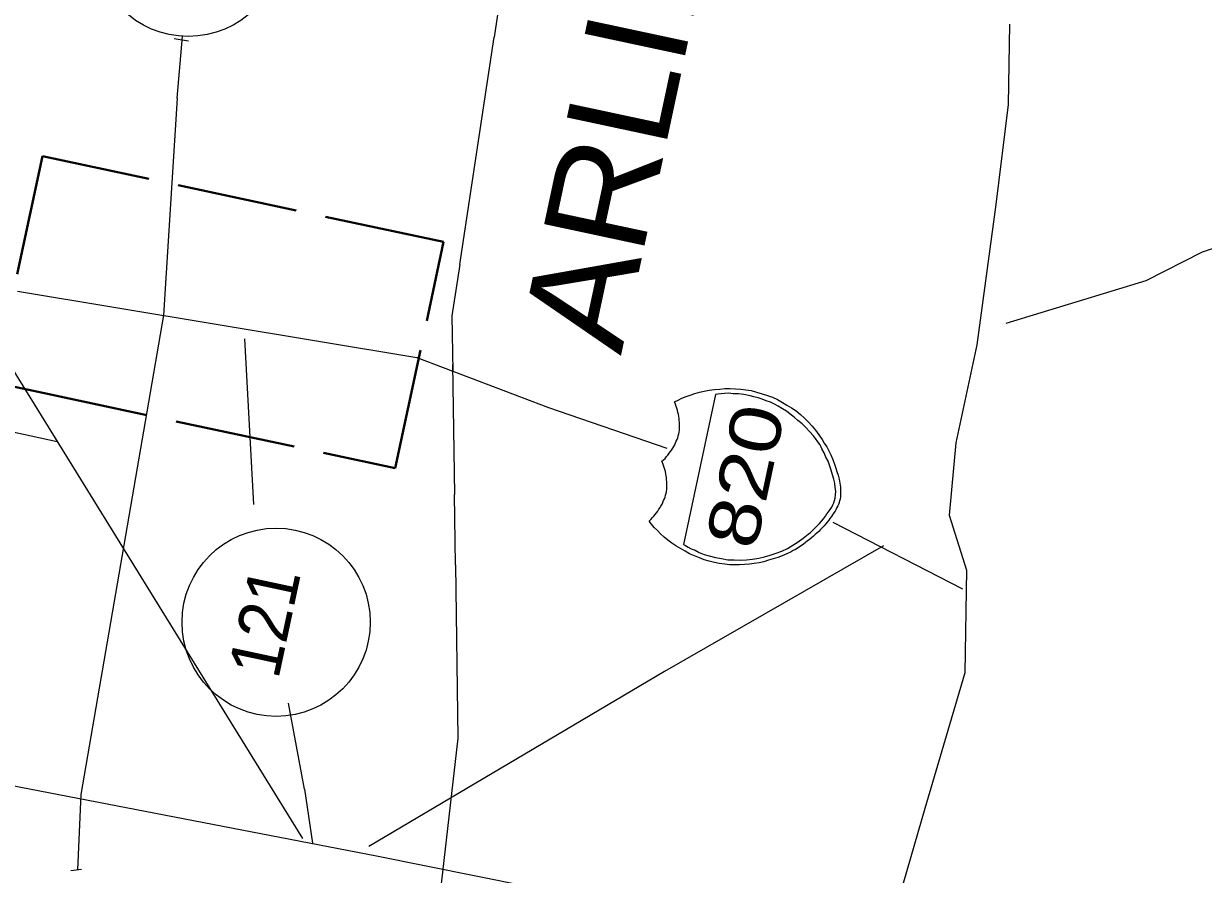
# Model space of a CAD drawing. Extents: x 2363411 to 2369126, y 6976878 to 6988319.
# Drawn here: x 2368256.8 to 2368374.1, y 6988001.5 to 6988086.1 of the extents above; entities that cross this region are included whole.
import ezdxf

# ---------------------------------------------------------------- set-up
doc = ezdxf.new("R2010")
doc.units = 0
doc.header["$LTSCALE"] = 2
doc.linetypes.add('LONG_DASHED', pattern=[7.5, 6, -1.5])
doc.layers.add('62', color=7, linetype='Continuous', lineweight=13)
doc.layers.add('63', color=7, linetype='Continuous', lineweight=13)

msp = doc.modelspace()

# ---------------------------------------------------------------- linework, layer by layer
at = {"layer": '62'}
for p, q in [((2368271.726, 6988084.644), (2368273.174, 6988084.427)), ((2368272.023, 6988078.711), (2368272.556, 6988084.857)), ((2368251.105, 6988059.091), (2368284.5, 6988005.083)), ((2368279.297, 6988044.991), (2368278.765, 6988054.79)), ((2368260.099, 6988044.536), (2368217.211, 6988053.7)), ((2368279.66, 6988038.309), (2368279.297, 6988044.991)), ((2368284.694, 6988009.968), (2368283.095, 6988018.521)), ((2368284.694, 6988009.968), (2368285.506, 6988004.616)), ((2368261.454, 6988001.884), (2368262.52, 6988002.024))]:
    msp.add_line(p, q, dxfattribs=at)
at = {"layer": '62', "lineweight": 25}
for p, q in [((2368300.149, 6988062.161), (2368303.557, 6988084.792)), ((2368256.14, 6988059.509), (2368295.872, 6988052.907)), ((2368299.434, 6988052.239), (2368299.614, 6988039.292)), ((2368299.708, 6988032.302), (2368299.614, 6988039.292)), ((2368337.269, 6988036.539), (2368350.16, 6988029.897))]:
    msp.add_line(p, q, dxfattribs=at)
for points in [[(2368327.726, 6988245.598), (2368326.234, 6988232.478), (2368324.804, 6988212.33), (2368322.527, 6988188.217), (2368318.14, 6988162.623), (2368312.07, 6988134.214), (2368306.258, 6988102.807), (2368303.557, 6988084.792)], [(2368354.847, 6988086.071), (2368354.706, 6988078.095), (2368353.478, 6988068.142), (2368351.579, 6988054.188), (2368349.489, 6988044.419), (2368348.853, 6988037.238), (2368350.559, 6988031.767), (2368350.381, 6988021.564), (2368346.413, 6988008.054), (2368342.848, 6987995.677), (2368339.073, 6987982.102), (2368337.198, 6987959.861), (2368330.069, 6987939.962), (2368322.731, 6987924.248), (2368315.293, 6987915.601), (2368301.729, 6987915.346), (2368288.793, 6987918.11), (2368282.016, 6987917.625), (2368273.924, 6987924.441)], [(2368300.149, 6988062.161), (2368299.359, 6988057.063), (2368299.447, 6988051.545)], [(2368295.873, 6988052.908), (2368308.964, 6988047.947), (2368320.735, 6988043.915)], [(2368299.708, 6988032.302), (2368299.958, 6988015.057), (2368296.639, 6987986.06), (2368297.535, 6987963.227), (2368296.503, 6987956.453)], [(2368243.911, 6988012.604), (2368291.866, 6988003.347), (2368346.556, 6987992.355), (2368417.518, 6987983.635), (2368451.697, 6987993.151)]]:
    msp.add_lwpolyline(points, dxfattribs=at)
at = {"layer": '62'}
for points in [[(2368492.126, 6988150.482), (2368487.488, 6988143.215), (2368483.673, 6988134.181), (2368476.579, 6988118.002), (2368468.319, 6988109.277), (2368462.564, 6988103.439), (2368454.914, 6988095.96), (2368443.897, 6988089.32), (2368432.645, 6988085.443), (2368420.226, 6988082.021), (2368405.209, 6988076.579), (2368395.275, 6988071.108), (2368385.769, 6988067.316), (2368374.006, 6988063.41), (2368368.396, 6988060.537), (2368354.465, 6988056.288)], [(2368272.023, 6988078.711), (2368270.662, 6988057.143), (2368262.451, 6988009.45), (2368262.119, 6988001.973)], [(2368320.861, 6988043.219), (2368320.991, 6988043.4), (2368321.119, 6988043.556), (2368321.221, 6988043.719), (2368321.351, 6988043.897), (2368321.433, 6988044.064), (2368321.538, 6988044.226), (2368321.624, 6988044.416), (2368321.682, 6988044.585), (2368321.768, 6988044.774), (2368321.85, 6988044.94), (2368321.893, 6988045.14), (2368321.935, 6988045.337), (2368321.968, 6988045.492), (2368322.01, 6988045.689), (2368322.008, 6988045.896), (2368322.002, 6988046.082), (2368322.019, 6988046.264), (2368322.015, 6988046.469), (2368321.988, 6988046.661), (2368321.981, 6988046.845), (2368321.936, 6988047.063), (2368321.911, 6988047.275), (2368321.856, 6988047.448), (2368321.81, 6988047.665), (2368321.739, 6988047.864), (2368321.686, 6988048.059), (2368321.599, 6988048.282), (2368321.509, 6988048.51), (2368321.869, 6988048.689), (2368322.23, 6988048.863), (2368322.66, 6988049.048), (2368323.08, 6988049.187), (2368323.525, 6988049.323), (2368323.993, 6988049.476), (2368324.477, 6988049.58), (2368324.953, 6988049.662), (2368325.495, 6988049.73), (2368326.013, 6988049.781), (2368326.531, 6988049.83), (2368327.06, 6988049.834), (2368327.585, 6988049.813), (2368328.106, 6988049.77), (2368328.6, 6988049.711), (2368329.133, 6988049.622), (2368329.654, 6988049.486), (2368330.219, 6988049.318), (2368330.755, 6988049.136), (2368331.246, 6988048.964), (2368331.751, 6988048.739), (2368332.241, 6988048.45), (2368332.691, 6988048.195), (2368333.162, 6988047.908), (2368333.602, 6988047.608), (2368334.032, 6988047.239), (2368334.42, 6988046.903), (2368334.823, 6988046.518), (2368335.192, 6988046.094), (2368335.544, 6988045.695), (2368335.881, 6988045.233), (2368336.2, 6988044.776), (2368336.418, 6988044.404), (2368336.661, 6988044.031), (2368336.876, 6988043.64), (2368337.069, 6988043.253), (2368337.232, 6988042.825), (2368337.393, 6988042.402), (2368337.539, 6988042.003), (2368337.678, 6988041.583), (2368337.783, 6988041.215), (2368337.884, 6988040.825), (2368337.959, 6988040.418), (2368338.016, 6988040.038), (2368338.019, 6988039.737), (2368338.039, 6988039.389), (2368338.021, 6988039.094), (2368337.986, 6988038.823)], [(2368337.986, 6988038.823), (2368337.927, 6988038.654), (2368337.894, 6988038.5), (2368337.829, 6988038.305), (2368337.755, 6988038.161), (2368337.671, 6988037.995), (2368337.591, 6988037.828), (2368337.481, 6988037.645), (2368337.372, 6988037.458), (2368337.244, 6988037.283), (2368337.135, 6988037.097), (2368336.977, 6988036.9), (2368336.853, 6988036.744), (2368336.717, 6988036.542), (2368336.565, 6988036.366), (2368336.386, 6988036.175), (2368336.233, 6988036.002), (2368336.054, 6988035.809), (2368335.875, 6988035.618), (2368335.68, 6988035.453), (2368335.508, 6988035.304), (2368335.335, 6988035.134), (2368335.112, 6988034.953), (2368334.915, 6988034.786), (2368334.728, 6988034.667), (2368334.527, 6988034.478), (2368334.34, 6988034.357), (2368334.122, 6988034.197), (2368333.937, 6988034.075), (2368333.721, 6988033.937), (2368333.536, 6988033.817), (2368333.329, 6988033.722), (2368333.12, 6988033.605), (2368332.687, 6988033.397), (2368332.228, 6988033.196), (2368331.778, 6988033.039), (2368331.337, 6988032.904), (2368330.868, 6988032.751), (2368330.396, 6988032.598), (2368329.94, 6988032.511), (2368329.441, 6988032.436), (2368328.985, 6988032.349), (2368328.472, 6988032.322), (2368327.986, 6988032.309), (2368327.501, 6988032.298), (2368326.997, 6988032.312), (2368326.506, 6988032.372), (2368325.967, 6988032.442), (2368325.477, 6988032.522), (2368324.956, 6988032.656), (2368324.48, 6988032.805), (2368323.99, 6988032.979), (2368323.505, 6988033.197), (2368323.019, 6988033.395), (2368322.569, 6988033.651), (2368322.117, 6988033.907), (2368321.643, 6988034.172), (2368321.247, 6988034.463), (2368320.848, 6988034.755), (2368320.477, 6988035.061), (2368320.132, 6988035.39), (2368319.809, 6988035.713), (2368319.482, 6988036.012), (2368319.232, 6988036.343), (2368318.975, 6988036.652), (2368319.149, 6988036.821), (2368319.323, 6988036.991), (2368319.451, 6988037.147), (2368319.595, 6988037.301), (2368319.726, 6988037.479), (2368319.852, 6988037.636), (2368319.961, 6988037.822), (2368320.091, 6988038.001), (2368320.168, 6988038.146), (2368320.276, 6988038.329), (2368320.359, 6988038.496), (2368320.422, 6988038.687), (2368320.508, 6988038.877), (2368320.592, 6988039.043), (2368320.628, 6988039.219), (2368320.672, 6988039.418), (2368320.708, 6988039.595), (2368320.75, 6988039.792), (2368320.744, 6988039.98), (2368320.744, 6988040.184), (2368320.753, 6988040.344), (2368320.753, 6988040.551), (2368320.728, 6988040.762), (2368320.726, 6988040.971), (2368320.671, 6988041.143), (2368320.646, 6988041.357), (2368320.601, 6988041.573), (2368320.55, 6988041.768), (2368320.481, 6988041.969), (2368320.433, 6988042.183), (2368320.335, 6988042.368), (2368320.249, 6988042.613), (2368320.414, 6988042.74), (2368320.583, 6988042.888), (2368320.713, 6988043.066), (2368320.861, 6988043.219)], [(2368342.308, 6988034.174), (2368320.517, 6988021.687), (2368291.1, 6988004.294)]]:
    msp.add_lwpolyline(points, dxfattribs=at)
at = {"layer": '62', "linetype": 'LONG_DASHED', "lineweight": 40}
msp.add_lwpolyline([(2368257.265, 6988049.698), (2368293.728, 6988041.907), (2368298.54, 6988064.419), (2368258.623, 6988072.948), (2368253.811, 6988050.436)], close=True, dxfattribs=at)
at = {"layer": '62'}
msp.add_lwpolyline([(2368325.596, 6988049.226), (2368322.414, 6988034.328), (2368322.618, 6988034.213), (2368322.881, 6988034.042), (2368323.17, 6988033.89), (2368323.553, 6988033.739), (2368323.969, 6988033.536), (2368324.453, 6988033.316), (2368324.974, 6988033.182), (2368325.586, 6988033.029), (2368326.187, 6988032.923), (2368326.827, 6988032.808), (2368327.445, 6988032.793), (2368328.063, 6988032.775), (2368328.69, 6988032.803), (2368329.257, 6988032.866), (2368329.896, 6988032.958), (2368330.476, 6988033.09), (2368331.042, 6988033.245), (2368331.613, 6988033.442), (2368332.193, 6988033.668), (2368332.75, 6988033.917), (2368333.279, 6988034.24), (2368333.813, 6988034.586), (2368334.308, 6988034.961), (2368334.809, 6988035.361), (2368335.048, 6988035.516), (2368335.259, 6988035.75), (2368335.514, 6988035.971), (2368335.724, 6988036.202), (2368335.93, 6988036.41), (2368336.139, 6988036.641), (2368336.328, 6988036.877), (2368336.521, 6988037.136), (2368336.683, 6988037.355), (2368336.845, 6988037.572), (2368337.012, 6988037.813), (2368337.151, 6988038.037), (2368337.27, 6988038.265), (2368337.359, 6988038.475), (2368337.432, 6988038.711), (2368337.503, 6988038.929), (2368337.526, 6988039.245), (2368337.56, 6988039.628), (2368337.499, 6988039.987), (2368337.456, 6988040.434), (2368337.379, 6988040.818), (2368337.243, 6988041.261), (2368337.107, 6988041.705), (2368336.966, 6988042.126), (2368336.793, 6988042.6), (2368336.581, 6988043.014), (2368336.392, 6988043.422), (2368336.183, 6988043.835), (2368335.989, 6988044.22), (2368335.781, 6988044.54), (2368335.55, 6988044.866), (2368335.352, 6988045.117), (2368334.959, 6988045.544), (2368334.584, 6988045.948), (2368334.2, 6988046.306), (2368333.795, 6988046.668), (2368333.426, 6988047.001), (2368333.028, 6988047.292), (2368332.652, 6988047.579), (2368332.245, 6988047.828), (2368331.838, 6988048.076), (2368331.466, 6988048.27), (2368331.051, 6988048.474), (2368330.643, 6988048.608), (2368330.236, 6988048.762), (2368329.829, 6988048.896), (2368329.416, 6988049.007), (2368329.024, 6988049.113), (2368328.402, 6988049.224), (2368327.864, 6988049.294), (2368327.34, 6988049.314), (2368326.89, 6988049.363), (2368326.471, 6988049.34), (2368326.14, 6988049.294), (2368325.836, 6988049.267)], close=True, dxfattribs=at)
for centre in [(2368273.134, 6988094.221), (2368281.877, 6988026.586)]:
    msp.add_circle(centre, 9.364, dxfattribs=at)
at = {"layer": '63'}
for p, q in [((2368271.726, 6988084.644), (2368273.174, 6988084.427)), ((2368272.023, 6988078.711), (2368272.556, 6988084.857)), ((2368251.105, 6988059.091), (2368284.5, 6988005.083)), ((2368279.297, 6988044.991), (2368278.765, 6988054.79)), ((2368260.099, 6988044.536), (2368217.211, 6988053.7)), ((2368279.66, 6988038.309), (2368279.297, 6988044.991)), ((2368284.694, 6988009.968), (2368283.095, 6988018.521)), ((2368284.694, 6988009.968), (2368285.506, 6988004.616)), ((2368261.454, 6988001.884), (2368262.52, 6988002.024))]:
    msp.add_line(p, q, dxfattribs=at)
at = {"layer": '63', "lineweight": 25}
for p, q in [((2368300.149, 6988062.161), (2368303.557, 6988084.792)), ((2368256.14, 6988059.509), (2368295.872, 6988052.907)), ((2368299.434, 6988052.239), (2368299.614, 6988039.292)), ((2368299.708, 6988032.302), (2368299.614, 6988039.292)), ((2368337.269, 6988036.539), (2368350.16, 6988029.897))]:
    msp.add_line(p, q, dxfattribs=at)
for points in [[(2368327.726, 6988245.598), (2368326.234, 6988232.478), (2368324.804, 6988212.33), (2368322.527, 6988188.217), (2368318.14, 6988162.623), (2368312.07, 6988134.214), (2368306.258, 6988102.807), (2368303.557, 6988084.792)], [(2368354.847, 6988086.071), (2368354.706, 6988078.095), (2368353.478, 6988068.142), (2368351.579, 6988054.188), (2368349.489, 6988044.419), (2368348.853, 6988037.238), (2368350.559, 6988031.767), (2368350.381, 6988021.564), (2368346.413, 6988008.054), (2368342.848, 6987995.677), (2368339.073, 6987982.102), (2368337.198, 6987959.861), (2368330.069, 6987939.962), (2368322.731, 6987924.248), (2368315.293, 6987915.601), (2368301.729, 6987915.346), (2368288.793, 6987918.11), (2368282.016, 6987917.625), (2368273.924, 6987924.441)], [(2368300.149, 6988062.161), (2368299.359, 6988057.063), (2368299.447, 6988051.545)], [(2368295.873, 6988052.908), (2368308.964, 6988047.947), (2368320.735, 6988043.915)], [(2368299.708, 6988032.302), (2368299.958, 6988015.057), (2368296.639, 6987986.06), (2368297.535, 6987963.227), (2368296.503, 6987956.453)], [(2368243.911, 6988012.604), (2368291.866, 6988003.347), (2368346.556, 6987992.355), (2368417.518, 6987983.635), (2368451.697, 6987993.151)]]:
    msp.add_lwpolyline(points, dxfattribs=at)
at = {"layer": '63'}
for points in [[(2368492.126, 6988150.482), (2368487.488, 6988143.215), (2368483.673, 6988134.181), (2368476.579, 6988118.002), (2368468.319, 6988109.277), (2368462.564, 6988103.439), (2368454.914, 6988095.96), (2368443.897, 6988089.32), (2368432.645, 6988085.443), (2368420.226, 6988082.021), (2368405.209, 6988076.579), (2368395.275, 6988071.108), (2368385.769, 6988067.316), (2368374.006, 6988063.41), (2368368.396, 6988060.537), (2368354.465, 6988056.288)], [(2368272.023, 6988078.711), (2368270.662, 6988057.143), (2368262.451, 6988009.45), (2368262.119, 6988001.973)], [(2368320.861, 6988043.219), (2368320.991, 6988043.4), (2368321.119, 6988043.556), (2368321.221, 6988043.719), (2368321.351, 6988043.897), (2368321.433, 6988044.064), (2368321.538, 6988044.226), (2368321.624, 6988044.416), (2368321.682, 6988044.585), (2368321.768, 6988044.774), (2368321.85, 6988044.94), (2368321.893, 6988045.14), (2368321.935, 6988045.337), (2368321.968, 6988045.492), (2368322.01, 6988045.689), (2368322.008, 6988045.896), (2368322.002, 6988046.082), (2368322.019, 6988046.264), (2368322.015, 6988046.469), (2368321.988, 6988046.661), (2368321.981, 6988046.845), (2368321.936, 6988047.063), (2368321.911, 6988047.275), (2368321.856, 6988047.448), (2368321.81, 6988047.665), (2368321.739, 6988047.864), (2368321.686, 6988048.059), (2368321.599, 6988048.282), (2368321.509, 6988048.51), (2368321.869, 6988048.689), (2368322.23, 6988048.863), (2368322.66, 6988049.048), (2368323.08, 6988049.187), (2368323.525, 6988049.323), (2368323.993, 6988049.476), (2368324.477, 6988049.58), (2368324.953, 6988049.662), (2368325.495, 6988049.73), (2368326.013, 6988049.781), (2368326.531, 6988049.83), (2368327.06, 6988049.834), (2368327.585, 6988049.813), (2368328.106, 6988049.77), (2368328.6, 6988049.711), (2368329.133, 6988049.622), (2368329.654, 6988049.486), (2368330.219, 6988049.318), (2368330.755, 6988049.136), (2368331.246, 6988048.964), (2368331.751, 6988048.739), (2368332.241, 6988048.45), (2368332.691, 6988048.195), (2368333.162, 6988047.908), (2368333.602, 6988047.608), (2368334.032, 6988047.239), (2368334.42, 6988046.903), (2368334.823, 6988046.518), (2368335.192, 6988046.094), (2368335.544, 6988045.695), (2368335.881, 6988045.233), (2368336.2, 6988044.776), (2368336.418, 6988044.404), (2368336.661, 6988044.031), (2368336.876, 6988043.64), (2368337.069, 6988043.253), (2368337.232, 6988042.825), (2368337.393, 6988042.402), (2368337.539, 6988042.003), (2368337.678, 6988041.583), (2368337.783, 6988041.215), (2368337.884, 6988040.825), (2368337.959, 6988040.418), (2368338.016, 6988040.038), (2368338.019, 6988039.737), (2368338.039, 6988039.389), (2368338.021, 6988039.094), (2368337.986, 6988038.823)], [(2368337.986, 6988038.823), (2368337.927, 6988038.654), (2368337.894, 6988038.5), (2368337.829, 6988038.305), (2368337.755, 6988038.161), (2368337.671, 6988037.995), (2368337.591, 6988037.828), (2368337.481, 6988037.645), (2368337.372, 6988037.458), (2368337.244, 6988037.283), (2368337.135, 6988037.097), (2368336.977, 6988036.9), (2368336.853, 6988036.744), (2368336.717, 6988036.542), (2368336.565, 6988036.366), (2368336.386, 6988036.175), (2368336.233, 6988036.002), (2368336.054, 6988035.809), (2368335.875, 6988035.618), (2368335.68, 6988035.453), (2368335.508, 6988035.304), (2368335.335, 6988035.134), (2368335.112, 6988034.953), (2368334.915, 6988034.786), (2368334.728, 6988034.667), (2368334.527, 6988034.478), (2368334.34, 6988034.357), (2368334.122, 6988034.197), (2368333.937, 6988034.075), (2368333.721, 6988033.937), (2368333.536, 6988033.817), (2368333.329, 6988033.722), (2368333.12, 6988033.605), (2368332.687, 6988033.397), (2368332.228, 6988033.196), (2368331.778, 6988033.039), (2368331.337, 6988032.904), (2368330.868, 6988032.751), (2368330.396, 6988032.598), (2368329.94, 6988032.511), (2368329.441, 6988032.436), (2368328.985, 6988032.349), (2368328.472, 6988032.322), (2368327.986, 6988032.309), (2368327.501, 6988032.298), (2368326.997, 6988032.312), (2368326.506, 6988032.372), (2368325.967, 6988032.442), (2368325.477, 6988032.522), (2368324.956, 6988032.656), (2368324.48, 6988032.805), (2368323.99, 6988032.979), (2368323.505, 6988033.197), (2368323.019, 6988033.395), (2368322.569, 6988033.651), (2368322.117, 6988033.907), (2368321.643, 6988034.172), (2368321.247, 6988034.463), (2368320.848, 6988034.755), (2368320.477, 6988035.061), (2368320.132, 6988035.39), (2368319.809, 6988035.713), (2368319.482, 6988036.012), (2368319.232, 6988036.343), (2368318.975, 6988036.652), (2368319.149, 6988036.821), (2368319.323, 6988036.991), (2368319.451, 6988037.147), (2368319.595, 6988037.301), (2368319.726, 6988037.479), (2368319.852, 6988037.636), (2368319.961, 6988037.822), (2368320.091, 6988038.001), (2368320.168, 6988038.146), (2368320.276, 6988038.329), (2368320.359, 6988038.496), (2368320.422, 6988038.687), (2368320.508, 6988038.877), (2368320.592, 6988039.043), (2368320.628, 6988039.219), (2368320.672, 6988039.418), (2368320.708, 6988039.595), (2368320.75, 6988039.792), (2368320.744, 6988039.98), (2368320.744, 6988040.184), (2368320.753, 6988040.344), (2368320.753, 6988040.551), (2368320.728, 6988040.762), (2368320.726, 6988040.971), (2368320.671, 6988041.143), (2368320.646, 6988041.357), (2368320.601, 6988041.573), (2368320.55, 6988041.768), (2368320.481, 6988041.969), (2368320.433, 6988042.183), (2368320.335, 6988042.368), (2368320.249, 6988042.613), (2368320.414, 6988042.74), (2368320.583, 6988042.888), (2368320.713, 6988043.066), (2368320.861, 6988043.219)], [(2368342.308, 6988034.174), (2368320.517, 6988021.687), (2368291.1, 6988004.294)]]:
    msp.add_lwpolyline(points, dxfattribs=at)
at = {"layer": '63', "linetype": 'LONG_DASHED', "lineweight": 40}
msp.add_lwpolyline([(2368257.265, 6988049.698), (2368293.728, 6988041.907), (2368298.54, 6988064.419), (2368258.623, 6988072.948), (2368253.811, 6988050.436)], close=True, dxfattribs=at)
at = {"layer": '63'}
msp.add_lwpolyline([(2368325.596, 6988049.226), (2368322.414, 6988034.328), (2368322.618, 6988034.213), (2368322.881, 6988034.042), (2368323.17, 6988033.89), (2368323.553, 6988033.739), (2368323.969, 6988033.536), (2368324.453, 6988033.316), (2368324.974, 6988033.182), (2368325.586, 6988033.029), (2368326.187, 6988032.923), (2368326.827, 6988032.808), (2368327.445, 6988032.793), (2368328.063, 6988032.775), (2368328.69, 6988032.803), (2368329.257, 6988032.866), (2368329.896, 6988032.958), (2368330.476, 6988033.09), (2368331.042, 6988033.245), (2368331.613, 6988033.442), (2368332.193, 6988033.668), (2368332.75, 6988033.917), (2368333.279, 6988034.24), (2368333.813, 6988034.586), (2368334.308, 6988034.961), (2368334.809, 6988035.361), (2368335.048, 6988035.516), (2368335.259, 6988035.75), (2368335.514, 6988035.971), (2368335.724, 6988036.202), (2368335.93, 6988036.41), (2368336.139, 6988036.641), (2368336.328, 6988036.877), (2368336.521, 6988037.136), (2368336.683, 6988037.355), (2368336.845, 6988037.572), (2368337.012, 6988037.813), (2368337.151, 6988038.037), (2368337.27, 6988038.265), (2368337.359, 6988038.475), (2368337.432, 6988038.711), (2368337.503, 6988038.929), (2368337.526, 6988039.245), (2368337.56, 6988039.628), (2368337.499, 6988039.987), (2368337.456, 6988040.434), (2368337.379, 6988040.818), (2368337.243, 6988041.261), (2368337.107, 6988041.705), (2368336.966, 6988042.126), (2368336.793, 6988042.6), (2368336.581, 6988043.014), (2368336.392, 6988043.422), (2368336.183, 6988043.835), (2368335.989, 6988044.22), (2368335.781, 6988044.54), (2368335.55, 6988044.866), (2368335.352, 6988045.117), (2368334.959, 6988045.544), (2368334.584, 6988045.948), (2368334.2, 6988046.306), (2368333.795, 6988046.668), (2368333.426, 6988047.001), (2368333.028, 6988047.292), (2368332.652, 6988047.579), (2368332.245, 6988047.828), (2368331.838, 6988048.076), (2368331.466, 6988048.27), (2368331.051, 6988048.474), (2368330.643, 6988048.608), (2368330.236, 6988048.762), (2368329.829, 6988048.896), (2368329.416, 6988049.007), (2368329.024, 6988049.113), (2368328.402, 6988049.224), (2368327.864, 6988049.294), (2368327.34, 6988049.314), (2368326.89, 6988049.363), (2368326.471, 6988049.34), (2368326.14, 6988049.294), (2368325.836, 6988049.267)], close=True, dxfattribs=at)
for centre in [(2368273.134, 6988094.221), (2368281.877, 6988026.586)]:
    msp.add_circle(centre, 9.364, dxfattribs=at)

# ---------------------------------------------------------------- texts
at = {"layer": '62'}
for s, height, width, p in [('ARLINGTON', 10.21, 1.1, (2368316.177, 6988053.058)), ('820', 5.099, 1.25, (2368329.563, 6988033.652)), ('121', 5.099, 0.95, (2368282.087, 6988020.811))]:
    msp.add_text(s, height=height, rotation=77.939, dxfattribs=dict(at, width=width)).set_placement(p)
at = {"layer": '63'}
for s, height, width, p in [('ARLINGTON', 10.21, 1.1, (2368316.177, 6988053.058)), ('820', 5.099, 1.25, (2368329.563, 6988033.652)), ('121', 5.099, 0.95, (2368282.087, 6988020.811))]:
    msp.add_text(s, height=height, rotation=77.939, dxfattribs=dict(at, width=width)).set_placement(p)

doc.saveas('drawing.dxf')
